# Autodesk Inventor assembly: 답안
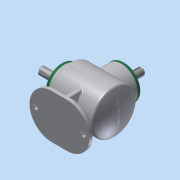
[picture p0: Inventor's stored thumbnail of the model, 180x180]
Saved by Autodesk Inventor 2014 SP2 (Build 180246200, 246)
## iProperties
Created: 2016-04
Part Number: 답안
Document SubType Name: Assembly
Designer: SCD-A19
Author: SCD-A19
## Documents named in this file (14)
- C:\Users\SCD-A19\Desktop\460407V1008\답안.iam
- C:\Users\SCD-A19\Desktop\460407V1008\M4.ipt
- C:\Users\SCD-A19\Desktop\460407V1008\메인 베벨기어.ipt
- C:\Users\SCD-A19\Desktop\460407V1008\메인 축.ipt
- 메인 축.ipt
- C:\Users\SCD-A19\Desktop\460407V1008\베어링 6203.ipt
- C:\Users\SCD-A19\Desktop\460407V1008\본체.ipt
- C:\Users\SCD-A19\Desktop\460407V1008\서브 베벨기어.ipt
- C:\Users\SCD-A19\Desktop\460407V1008\서브 축.ipt
- 서브 축.ipt
- C:\Users\SCD-A19\Desktop\460407V1008\오일실 17 32 8.ipt
- C:\Users\SCD-A19\Desktop\460407V1008\커버.ipt
- C:\Users\SCD-A19\Desktop\460407V1008\키 4x4.ipt
- C:\Users\SCD-A19\Desktop\460407V1008\키 5x5.ipt
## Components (8 placed, 1 different names)
1. M4:1
2. M4:2
3. M4:3
4. M4:4
5. M4:5
6. M4:6
7. M4:7
8. M4:8
